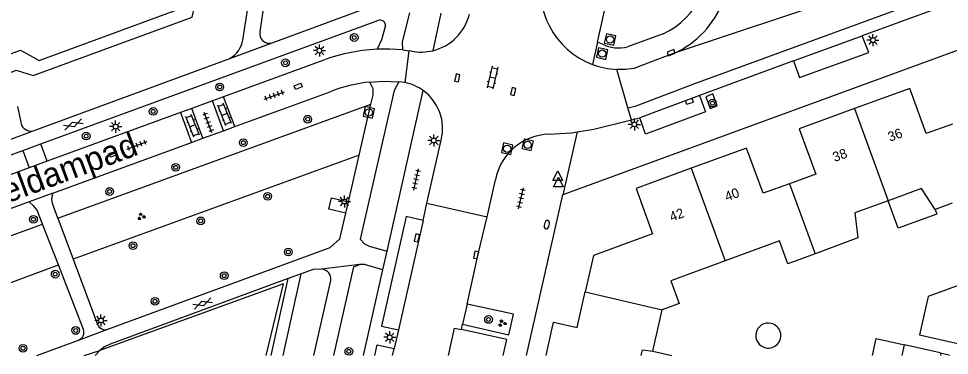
# Model space of a CAD drawing. Extents: x 128000 to 131008, y 398996 to 402500.
# Drawn here: x 129057.3 to 129153.7, y 399000 to 399034.9 of the extents above; entities that cross this region are included whole.
import ezdxf

# ---------------------------------------------------------------- set-up
doc = ezdxf.new("R2010")
doc.units = 0
for name, color, linetype in [('gg-afsc-hekwerk', 7, 'Continuous'), ('gg-anno-huisnummerreeks BGT', 7, 'Continuous'), ('gg-anno-openbare ruimte label', 7, 'Continuous'), ('gg-bbg-gedigitaliseerde bijgebouw', 7, 'Continuous'), ('gg-bbg-hoofdgebouw', 7, 'Continuous'), ('gg-bbg-luifel en loopbrug', 7, 'Continuous'), ('gg-bbg-tussenscheiding', 7, 'Continuous'), ('gg-knt-BGT kruinlijn', 7, 'Continuous'), ('gg-knt-verharding', 7, 'Continuous'), ('gg-knt-verharding nz', 7, 'Continuous'), ('gg-kntw-beschoeiing', 7, 'Continuous'), ('gt-grn-groengrens', 7, 'Continuous'), ('gt-grn-weggrens', 7, 'Continuous'), ('gt-symb-boom', 7, 'Continuous'), ('gt-symb-brandkraan', 7, 'Continuous'), ('gt-symb-gesloten verharding', 7, 'Continuous'), ('gt-symb-groenvak', 7, 'Continuous'), ('gt-symb-klinker verharding', 7, 'Continuous'), ('gt-symb-kolk', 7, 'Continuous'), ('gt-symb-kolk center center', 7, 'Continuous'), ('gt-symb-lichtmast', 7, 'Continuous'), ('gt-symb-rioolschacht', 7, 'Continuous'), ('gt-symb-tegel verharding', 7, 'Continuous'), ('gt-symb-waterafsluiter', 7, 'Continuous')]:
    doc.layers.add(name, color=color, linetype=linetype)

# ---------------------------------------------------------------- blocks, each defined once
blk = doc.blocks.new('gt0-KOLK')
at = {"layer": 'gt-symb-kolk'}
blk.add_lwpolyline([(0, 0), (0.375, 0), (0.375, 0.4), (-0.375, 0.4), (-0.375, 0), (0, 0)], dxfattribs=at)
blk = doc.blocks.new('gt0-KL1')
at = {"layer": 'gt-symb-klinker verharding'}
for p, q in [((-1.15, 0.3), (1.15, 0.3)), ((-1, -0.3), (-1, 0.3)), ((-0.5, 0.3), (-0.5, 0.45)), ((0, -0.3), (0, 0.3)), ((0.5, 0.3), (0.5, 0.45)), ((1, -0.3), (1, 0.3)), ((-1.15, -0.3), (1.15, -0.3)), ((-0.5, -0.45), (-0.5, -0.3)), ((0.5, -0.45), (0.5, -0.3))]:
    blk.add_line(p, q, dxfattribs=at)
blk = doc.blocks.new('gt0-RS')
at = {"layer": 'gt-symb-rioolschacht'}
blk.add_lwpolyline([(-0.5, -0.5), (0.5, -0.5), (0.5, 0.5), (-0.5, 0.5)], close=True, dxfattribs=at)
blk.add_circle((0, 0), 0.375, dxfattribs=at)
blk = doc.blocks.new('gt0-LMAST')
at = {"layer": 'gt-symb-lichtmast'}
for p, q in [((-0.182, 0.173), (-0.447, 0.438)), ((-0.005, 0.246), (-0.005, 0.621)), ((0.172, 0.173), (0.437, 0.438)), ((-0.255, -0.004), (-0.63, -0.004)), ((-0.182, -0.181), (-0.447, -0.446)), ((-0.005, -0.254), (-0.005, -0.629)), ((0.437, -0.446), (0.172, -0.181)), ((0.245, -0.004), (0.62, -0.004))]:
    blk.add_line(p, q, dxfattribs=at)
blk.add_circle((-0.005, -0.004), 0.25, dxfattribs=at)
blk = doc.blocks.new('gt0-BOOM')
at = {"layer": 'gt-symb-boom'}
for radius in [0.4, 0.2]:
    blk.add_circle((0, 0), radius, dxfattribs=at)
blk = doc.blocks.new('gt0-BR')
at = {"layer": 'gt-symb-brandkraan'}
for centre, radius, start, end in [((-0.244, 0), 0.206, 107.56694, 252.43307), ((0.599, -2.664), 3, 106.89205, 107.56694), ((0, -0.691), 0.938, 73.10799, 106.89205), ((-0.599, -2.664), 3, 72.43309, 73.10799), ((0.244, 0), 0.206, 287.56695, 72.43309), ((0.599, 2.664), 3, 252.43307, 253.10797), ((0, 0.691), 0.938, 253.10797, 286.89206), ((-0.599, 2.664), 3, 286.89206, 287.56695)]:
    blk.add_arc(centre, radius, start, end, dxfattribs=at)
blk = doc.blocks.new('gt0-TEG1')
at = {"layer": 'gt-symb-tegel verharding'}
for p, q in [((-1.125, 0), (1.125, 0)), ((-0.9, -0.25), (-0.9, 0.25)), ((-0.45, -0.25), (-0.45, 0.25)), ((0, -0.25), (0, 0.25)), ((0.45, -0.25), (0.45, 0.25)), ((0.9, -0.25), (0.9, 0.25))]:
    blk.add_line(p, q, dxfattribs=at)
blk = doc.blocks.new('gt0-WAFSL')
at = {"layer": 'gt-symb-waterafsluiter'}
for p, q in [((-0.5, -0.333), (0, 0.667)), ((0, 0.667), (0.5, -0.333)), ((0.5, -0.333), (-0.5, -0.333))]:
    blk.add_line(p, q, dxfattribs=at)
blk = doc.blocks.new('gt0-GRVAK')
at = {"layer": 'gt-symb-groenvak'}
for p, q in [((-0.11, 0.189), (-0.228, 0.24)), ((-0.182, 0.153), (0.088, 0.153)), ((-0.091, 0.211), (-0.156, 0.322)), ((-0.047, 0.214), (-0.047, 0.393)), ((-0.004, 0.211), (0.061, 0.322)), ((0.015, 0.189), (0.133, 0.24)), ((0.262, -0.052), (0.197, 0.059)), ((0.305, -0.049), (0.305, 0.13)), ((0.349, -0.052), (0.414, 0.059)), ((-0.245, -0.228), (-0.363, -0.177)), ((-0.318, -0.264), (-0.047, -0.264)), ((-0.226, -0.206), (-0.291, -0.095)), ((-0.183, -0.203), (-0.183, -0.024)), ((-0.139, -0.206), (-0.074, -0.095)), ((-0.12, -0.228), (-0.002, -0.177)), ((0.243, -0.074), (0.125, -0.023)), ((0.17, -0.11), (0.441, -0.11)), ((0.368, -0.074), (0.486, -0.023))]:
    blk.add_line(p, q, dxfattribs=at)
blk = doc.blocks.new('gt0-KOLKCC')
at = {"layer": 'gt-symb-kolk center center'}
blk.add_lwpolyline([(-0.375, 0.2), (0.375, 0.2), (0.375, -0.2), (-0.375, -0.2)], close=True, dxfattribs=at)
blk = doc.blocks.new('gt0-GESVH1')
at = {"layer": 'gt-symb-gesloten verharding'}
for p, q in [((-0.992, -0.261), (0.008, 0.239)), ((0.008, -0.261), (-0.992, 0.239)), ((0.008, 0.239), (1.008, -0.261)), ((1.008, 0.239), (0.008, -0.261))]:
    blk.add_line(p, q, dxfattribs=at)

msp = doc.modelspace()

# ---------------------------------------------------------------- linework, layer by layer
at = {"layer": 'gg-afsc-hekwerk'}
msp.add_lwpolyline([(129082.954, 399000), (129084.741, 399007.434), (129065.719, 399000.513)], dxfattribs=at)
at = {"layer": 'gg-bbg-gedigitaliseerde bijgebouw'}
for start, end in [(77.29161, 257.25829), (257.25828, 77.29162)]:
    msp.add_arc((129134.977, 399002.058), 1.298, start, end, dxfattribs=at)
at = {"layer": 'gg-bbg-hoofdgebouw'}
for p, q in [((129154.034, 399015.781), (129152.271, 399015.132)), ((129123.004, 399000.444), (129123.97, 399004.72)), ((129148.836, 399000), (129149.08, 399001.101)), ((129152.779, 399000.268), (129149.08, 399001.101)), ((129152.779, 399000.268), (129152.833, 399000))]:
    msp.add_line(p, q, dxfattribs=at)
for points in [[(129154.06, 399023.996), (129151.34, 399023.001), (129149.62, 399027.691), (129143.894, 399025.591)], [(129143.894, 399025.591), (129138.17, 399023.491), (129139.89, 399018.801), (129137.166, 399017.804)], [(129137.166, 399017.804), (129134.45, 399016.811), (129132.72, 399021.501), (129126.998, 399019.402)], [(129126.998, 399019.402), (129121.27, 399017.301), (129122.99, 399012.611), (129116.86, 399010.361), (129116.003, 399006.579)], [(129152.271, 399015.132), (129150.829, 399017.309), (129147.381, 399016.042)], [(129147.381, 399016.042), (129143.933, 399014.774), (129144.254, 399012.185), (129139.814, 399010.548)], [(129139.814, 399010.548), (129137, 399009.51), (129136.136, 399011.865), (129130.508, 399009.801)], [(129130.508, 399009.801), (129124.876, 399007.735), (129125.74, 399005.38), (129123.97, 399004.72)], [(129111.955, 399000), (129112.73, 399003.461), (129115.17, 399002.901), (129116.003, 399006.579)], [(129121.81, 399000), (129121.937, 399000.564), (129123.004, 399000.444)]]:
    msp.add_lwpolyline(points, dxfattribs=at)
at = {"layer": 'gg-bbg-luifel en loopbrug'}
msp.add_line((129123.004, 399000.444), (129124.969, 399000), dxfattribs=at)
for points in [[(129152.271, 399015.132), (129152.444, 399014.663), (129148.431, 399013.187), (129147.381, 399016.042)], [(129156.549, 399007.937), (129151.534, 399006.122), (129150.636, 399002.145), (129155.065, 399001.145)], [(129145.759, 399000), (129146.155, 399001.76), (129149.08, 399001.101)], [(129152.779, 399000.268), (129153.718, 399000.057), (129153.731, 399000)]]:
    msp.add_lwpolyline(points, dxfattribs=at)
at = {"layer": 'gg-bbg-tussenscheiding'}
for p, q in [((129143.894, 399025.591), (129147.381, 399016.042)), ((129126.998, 399019.402), (129130.508, 399009.801)), ((129137.166, 399017.804), (129139.814, 399010.548)), ((129116.003, 399006.579), (129123.97, 399004.72))]:
    msp.add_line(p, q, dxfattribs=at)
at = {"layer": 'gg-knt-BGT kruinlijn'}
for p, q in [((129080.547, 399032.698), (129081.516, 399038.935)), ((129058.92, 399023.31), (129079.187, 399030.793))]:
    msp.add_line(p, q, dxfattribs=at)
msp.add_arc((129077.81, 399033.214), 2.786, 299.63293, 349.32017, dxfattribs=at)
at = {"layer": 'gg-knt-verharding'}
for p, q in [((129185.53, 399043.001), (129113.69, 399016.651)), ((129117.27, 399032.471), (129119.229, 399041.215)), ((129083.125, 399039.274), (129082.309, 399033.567)), ((129155.387, 399037.07), (129144.695, 399033.15)), ((129101.059, 399035.483), (129100.214, 399031.601)), ((129059.615, 399021.936), (129094.541, 399034.73)), ((129124.07, 399033.361), (129120.39, 399032)), ((129117.8, 399032.271), (129117.27, 399032.471)), ((129097.1, 399031.691), (129097.781, 399031.594)), ((129097.351, 399028.3), (129097.781, 399031.594)), ((129098.02, 399031.561), (129097.781, 399031.594)), ((129088.46, 399030.461), (129078.55, 399026.831)), ((129125.24, 399031.331), (129121.057, 399029.749)), ((129137.576, 399030.54), (129127.833, 399026.967)), ((129120.439, 399025.691), (129119.288, 399029.652)), ((129097.351, 399028.3), (129096.7, 399028.367)), ((129078.55, 399026.831), (129077.388, 399026.406)), ((129079.723, 399023.733), (129078.55, 399026.831)), ((129079.723, 399023.733), (129089.602, 399027.351)), ((129095.484, 399010.826), (129099.233, 399027.462)), ((129057.187, 399025.809), (129057.62, 399023.891)), ((129077.388, 399026.406), (129075.251, 399025.623)), ((129078.531, 399023.296), (129077.388, 399026.406)), ((129092.589, 399020.765), (129093.805, 399026.042)), ((129120.805, 399024.432), (129120.439, 399025.691)), ((129074.069, 399025.19), (129060.273, 399020.137)), ((129075.251, 399025.623), (129074.069, 399025.19)), ((129074.069, 399025.19), (129075.23, 399022.087)), ((129076.413, 399022.521), (129075.251, 399025.623)), ((129078.531, 399023.296), (129079.723, 399023.733)), ((129120.805, 399024.432), (129121.674, 399024.649)), ((129076.413, 399022.521), (129078.531, 399023.296)), ((129057.736, 399021.247), (129059.615, 399021.936)), ((129060.848, 399016.82), (129075.23, 399022.087)), ((129075.23, 399022.087), (129076.413, 399022.521)), ((129099.617, 399015.791), (129101.09, 399022.331)), ((128999.736, 399000), (129057.736, 399021.247)), ((129060.273, 399020.137), (129058.394, 399019.449)), ((129091.476, 399015.934), (129092.589, 399020.765)), ((129058.394, 399019.449), (129040.257, 399012.806)), ((129105.835, 399014.381), (129106.701, 399018.222)), ((129060.848, 399016.82), (129058.407, 399015.926)), ((129109.939, 399000), (129113.69, 399016.651)), ((129058.407, 399015.926), (129041.407, 399009.7)), ((129091.206, 399014.764), (129091.476, 399015.934)), ((129099.214, 399014.002), (129099.617, 399015.791)), ((129099.617, 399015.791), (129105.835, 399014.381)), ((129061.374, 399014.23), (129062.954, 399009.99)), ((129061.437, 399009.376), (129059.799, 399013.6)), ((129095.047, 399008.888), (129095.484, 399010.826)), ((129064.027, 399002.701), (129061.437, 399009.376)), ((129062.954, 399009.99), (129065.48, 399003.215)), ((129086.588, 399008.461), (129085.245, 399007.967)), ((129093.045, 399000), (129095.047, 399008.888)), ((129087.897, 399000), (129089.661, 399007.761)), ((129103.782, 399005.306), (129103.298, 399003.226)), ((129096.658, 399002.654), (129096.218, 399000.7)), ((129103.186, 399002.677), (129103.298, 399003.226)), ((129059.195, 399000), (129063.531, 399001.596)), ((129065.245, 399000), (129065.719, 399000.513))]:
    msp.add_line(p, q, dxfattribs=at)
for points in [[(129083.563, 399032.409), (129094.89, 399036.591), (129095.74, 399037.161), (129096.52, 399038.461)], [(129097.1, 399031.691), (129097.08, 399032.531), (129097.85, 399035.531)], [(129095.33, 399034.211), (129094.92, 399032.741), (129094.45, 399031.749)], [(129137.576, 399030.54), (129138.208, 399028.808), (129145.372, 399031.422), (129144.695, 399033.15)], [(129097.1, 399031.691), (129095.776, 399031.767), (129094.45, 399031.749)], [(129121.057, 399029.749), (129120.175, 399029.653), (129119.288, 399029.652)], [(129096.7, 399028.367), (129096.21, 399027.461), (129092.7, 399012.061), (129093.16, 399011.581), (129093.63, 399011.331), (129095.484, 399010.826)], [(129093.701, 399028.352), (129095.085, 399028.433), (129096.7, 399028.367)], [(129093.805, 399026.042), (129094.031, 399027.021), (129094.031, 399027.631), (129093.701, 399028.352)], [(129127.833, 399026.967), (129128.474, 399025.244), (129122.26, 399022.948), (129121.674, 399024.649)], [(129128.512, 399026.821), (129128.957, 399025.611), (129129.674, 399025.89), (129129.245, 399027.116), (129128.512, 399026.821)], [(129115.168, 399023.183), (129116.91, 399023.461), (129120.805, 399024.432)], [(129112.25, 399022.941), (129114.591, 399023.091), (129115.168, 399023.183)], [(129061.374, 399014.23), (129060.843, 399015.653), (129060.755, 399016.157), (129060.848, 399016.82)], [(129059.799, 399013.6), (129059.232, 399015.06), (129058.903, 399015.461), (129058.407, 399015.926)], [(129066.567, 399002.713), (129089.58, 399011.181), (129090.59, 399012.091), (129091.206, 399014.764)], [(129099.214, 399014.002), (129097.457, 399014.393), (129094.906, 399003.041), (129096.658, 399002.654)], [(129103.782, 399005.306), (129104.898, 399010.373), (129105.835, 399014.381)], [(129089.959, 399000), (129092.04, 399009.181), (129092.61, 399009.441)], [(129095.047, 399008.888), (129093.15, 399009.441), (129092.61, 399009.441)], [(129088.72, 399008.931), (129087.84, 399008.921), (129086.588, 399008.461)], [(129085.245, 399007.967), (129066.791, 399001.18), (129066.226, 399000.893), (129065.719, 399000.513)], [(129103.298, 399003.226), (129108.105, 399002.136), (129108.569, 399004.262), (129103.782, 399005.306)], [(129107.518, 399000), (129107.888, 399001.639), (129103.186, 399002.677)], [(129094.21, 399000), (129094.457, 399001.096), (129096.218, 399000.7)]]:
    msp.add_lwpolyline(points, dxfattribs=at)
for centre, radius, start, end in [((129120.932, 399040.424), 7.729, 293.95255, 18.74651), ((129119.715, 399038.004), 8.362, 166.60402, 249.25041), ((129120.955, 399040.46), 10.084, 295.14617, 338.06112), ((129099.023, 399036.593), 5.132, 283.41572, 346.29671), ((129094.742, 399034.176), 0.589, 3.41265, 109.91394), ((129083.277, 399033.358), 0.991, 167.79514, 286.76331), ((129095.348, 399012.998), 18.773, 92.74333, 111.52718), ((129099.026, 399036.578), 5.117, 258.66259, 283.42636), ((129119.476, 399035.776), 3.885, 244.44605, 283.60734), ((129119.712, 399037.985), 8.344, 249.21945, 267.08523), ((129095.284, 399012.978), 15.455, 95.87759, 111.56915), ((129096.339, 399023.495), 4.911, 53.88946, 78.1065), ((129096.353, 399023.518), 4.884, 345.93172, 53.86046), ((129058.615, 399024.371), 1.105, 205.78433, 286.05373), ((129112.463, 399017.069), 5.876, 92.07536, 168.68189), ((129088.655, 399007.915), 1.018, 351.30145, 86.31615), ((129063.229, 399002.395), 0.854, 290.67209, 20.98026), ((129066.28, 399003.518), 0.855, 200.77671, 289.64627)]:
    msp.add_arc(centre, radius, start, end, dxfattribs=at)
at = {"layer": 'gg-knt-verharding nz'}
for p, q in [((129137.576, 399030.54), (129144.695, 399033.15)), ((129127.833, 399026.967), (129121.674, 399024.649)), ((129099.214, 399014.002), (129096.658, 399002.654)), ((129096.06, 399000), (129096.218, 399000.7))]:
    msp.add_line(p, q, dxfattribs=at)
for points in [[(129120.439, 399025.691), (129121.292, 399025.894), (129127.38, 399028.186), (129200.227, 399054.895)], [(129101.839, 399000), (129102.474, 399002.82), (129103.186, 399002.677)]]:
    msp.add_lwpolyline(points, dxfattribs=at)
at = {"layer": 'gg-kntw-beschoeiing'}
msp.add_lwpolyline([(129055.424, 399030.878), (129057.512, 399031.649), (129059.445, 399030.591), (129074.085, 399035.98), (129087.171, 399093.665), (129084.606, 399097.238), (129083.463, 399097.548)], dxfattribs=at)
at = {"layer": 'gt-grn-groengrens'}
for p, q in [((129061.374, 399014.23), (129093.805, 399026.042)), ((129060.273, 399020.137), (129059.615, 399021.936)), ((129057.736, 399021.247), (129058.394, 399019.449)), ((129092.589, 399020.765), (129062.954, 399009.99)), ((129021.994, 399000), (129059.799, 399013.6)), ((129035.851, 399000), (129061.437, 399009.376)), ((129084.713, 399000), (129086.588, 399008.461)), ((129083.48, 399000), (129085.245, 399007.967))]:
    msp.add_line(p, q, dxfattribs=at)
for points in [[(129056.048, 399029.167), (129057.061, 399029.589), (129058.83, 399029.031), (129075.302, 399035.08), (129088.889, 399093.804), (129085.725, 399098.178), (129082.453, 399098.957)], [(129091.206, 399014.764), (129089.448, 399015.167), (129089.716, 399016.337), (129091.476, 399015.934)]]:
    msp.add_lwpolyline(points, dxfattribs=at)
at = {"layer": 'gt-grn-weggrens'}
for p, q in [((129143.258, 399037.373), (129125.24, 399031.331)), ((129079.187, 399030.793), (129083.563, 399032.409)), ((129117.27, 399032.471), (129116.752, 399030.184)), ((129055.79, 399022.151), (129058.92, 399023.31)), ((129115.168, 399023.183), (129113.69, 399016.651)), ((129092.61, 399009.441), (129088.72, 399008.931)), ((129063.531, 399001.596), (129066.567, 399002.713)), ((129064.105, 399000), (129065.719, 399000.513))]:
    msp.add_line(p, q, dxfattribs=at)

# ---------------------------------------------------------------- block references
at = {"layer": 'gt-symb-boom'}
for p in [(129092.078, 399032.968), (129084.955, 399030.343), (129078.15, 399027.839), (129071.252, 399025.301), (129129.185, 399026.166), (129087.261, 399024.496), (129064.308, 399022.745), (129080.591, 399022.059), (129073.593, 399019.5), (129066.737, 399016.995), (129083.119, 399016.5), (129058.849, 399014.111), (129076.172, 399013.952), (129069.159, 399011.379), (129085.256, 399010.729), (129061.103, 399008.424), (129078.611, 399008.267), (129071.435, 399005.616), (129105.995, 399003.728), (129063.227, 399002.587), (129057.764, 399000.743), (129091.524, 399000.415)]:
    msp.add_blockref('gt0-BOOM', p, dxfattribs=at)
at = {"layer": 'gt-symb-brandkraan', "rotation": 77.2287574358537}
msp.add_blockref('gt0-BR', (129112.03, 399013.565), dxfattribs=at)
at = {"layer": 'gt-symb-gesloten verharding'}
for p, rotation in [((129062.959, 399023.945), 20.173944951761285), ((129076.374, 399005.391), 20.173944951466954)]:
    msp.add_blockref('gt0-GESVH1', p, dxfattribs=dict(at, rotation=rotation))
at = {"layer": 'gt-symb-groenvak'}
for p in [(129070.013, 399014.409), (129107.397, 399003.334)]:
    msp.add_blockref('gt0-GRVAK', p, dxfattribs=at)
at = {"layer": 'gt-symb-klinker verharding'}
for p, rotation in [((129106.409, 399028.821), -102.70273191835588), ((129078.651, 399024.993), 111.58865227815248), ((129075.33, 399023.81), 111.71629047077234)]:
    msp.add_blockref('gt0-KL1', p, dxfattribs=dict(at, rotation=rotation))
at = {"layer": 'gt-symb-kolk'}
for p, rotation in [((129124.989, 399031.214), 21.535364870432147), ((129102.555, 399028.821), -101.29870021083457), ((129108.744, 399027.326), 77.2287574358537), ((129126.738, 399026.537), -161.40202220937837), ((129098.759, 399012.143), 77.52092819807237), ((129104.898, 399010.373), 77.58922528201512)]:
    msp.add_blockref('gt0-KOLK', p, dxfattribs=dict(at, rotation=rotation))
at = {"layer": 'gt-symb-kolk center center'}
for p, rotation in [((129086.262, 399027.902), 20.173944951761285), ((129067.116, 399020.863), 18.12681251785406)]:
    msp.add_blockref('gt0-KOLKCC', p, dxfattribs=dict(at, rotation=rotation))
at = {"layer": 'gt-symb-lichtmast'}
for p in [(129145.82, 399032.695), (129088.477, 399031.613), (129067.369, 399023.726), (129121.104, 399023.962), (129100.323, 399022.296), (129091.064, 399015.959), (129065.851, 399003.633), (129095.761, 399001.88)]:
    msp.add_blockref('gt0-LMAST', p, dxfattribs=at)
at = {"layer": 'gt-symb-rioolschacht'}
for p, rotation in [((129118.586, 399032.766), -103.06333733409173), ((129117.761, 399031.301), -103.06333733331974), ((129093.594, 399025.196), -103.06333733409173), ((129107.925, 399021.432), -103.06333733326), ((129110.044, 399021.834), -103.06333733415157)]:
    msp.add_blockref('gt0-RS', p, dxfattribs=dict(at, rotation=rotation))
at = {"layer": 'gt-symb-tegel verharding'}
for p, rotation in [((129083.798, 399026.963), 20.120165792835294), ((129076.936, 399024.152), 110.55604521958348), ((129069.57, 399021.79), 20.06634962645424), ((129098.506, 399018.241), 77.22875743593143), ((129109.36, 399016.286), 77.22875743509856)]:
    msp.add_blockref('gt0-TEG1', p, dxfattribs=dict(at, rotation=rotation))
at = {"layer": 'gt-symb-waterafsluiter'}
for p in [(129113.163, 399018.468), (129113.231, 399017.811)]:
    msp.add_blockref('gt0-WAFSL', p, dxfattribs=at)

# ---------------------------------------------------------------- texts
at = {"layer": 'gg-anno-huisnummerreeks BGT'}
for s, p in [('36', (129147.578, 399022.15)), ('38', (129141.854, 399020.05)), ('40', (129130.68, 399015.961)), ('42', (129124.957, 399013.862))]:
    msp.add_text(s, height=1, rotation=20.1, dxfattribs=at).set_placement(p)
at = {"layer": 'gg-anno-openbare ruimte label'}
msp.add_text('Dubbeldampad', height=2.5, rotation=20.4, dxfattribs=at).set_placement((129048.608, 399012.96))

doc.saveas('drawing.dxf')
